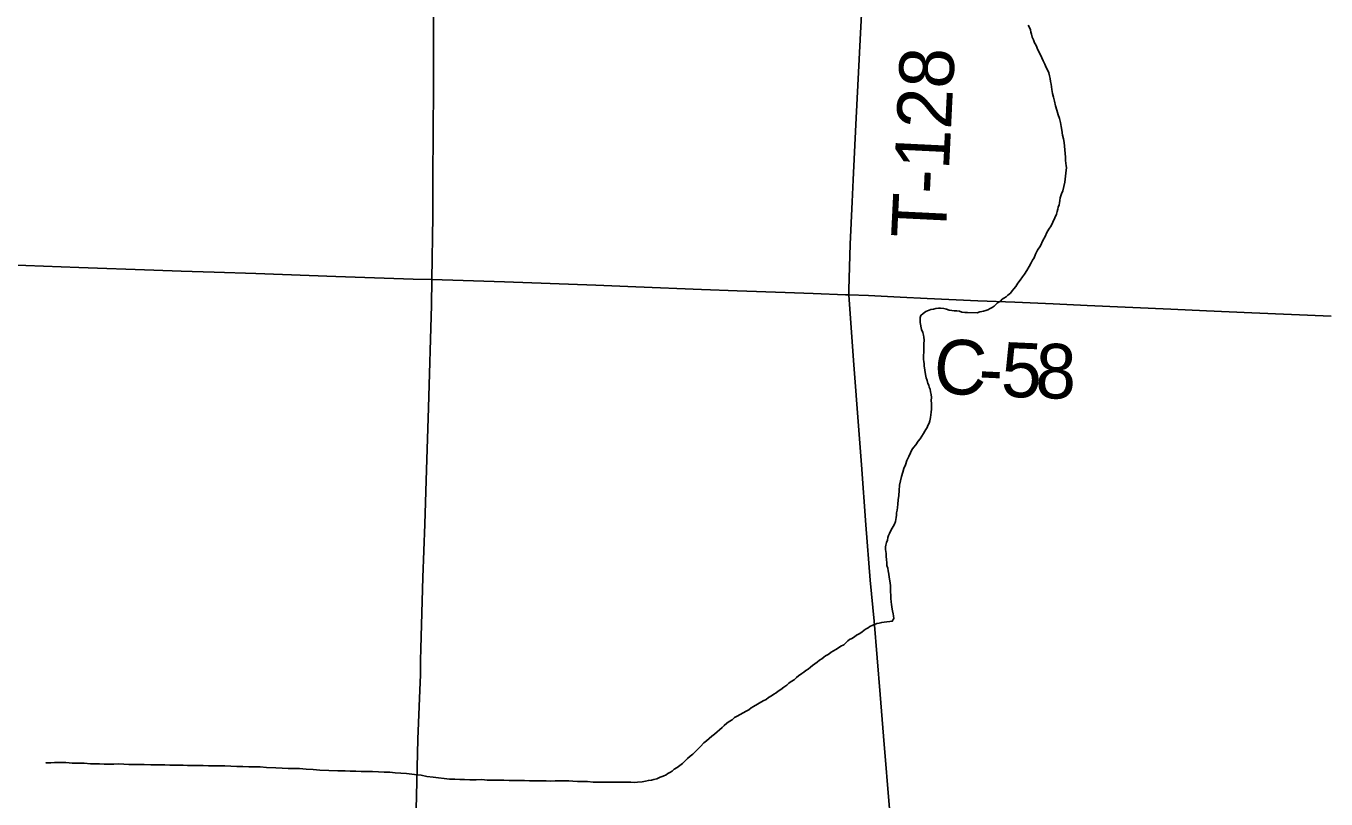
# Model space of a CAD drawing. Extents: x 2.1 to 73.9, y 4 to 26.
# Drawn here: x 43.974 to 44.65, y 24.1 to 24.503 of the extents above; entities that cross this region are included whole.
import ezdxf

# ---------------------------------------------------------------- set-up
doc = ezdxf.new("R2010")
doc.units = 0
for name, color, linetype in [('GM_X_County_Road', 7, 'Continuous'), ('GM_X_County_Road_Text', 7, 'Continuous'), ('GM_X_Minor_River', 7, 'Continuous'), ('GM_X_Township_Road', 7, 'Continuous'), ('GM_X_Township_Road_Text', 7, 'Continuous'), ('GM_X_US_Route', 7, 'Continuous')]:
    doc.layers.add(name, color=color, linetype=linetype)

msp = doc.modelspace()

# ---------------------------------------------------------------- linework, layer by layer
at = {"layer": 'GM_X_County_Road'}
for points in [[(43.67911, 24.38566), (43.68693, 24.38705), (43.69061, 24.38748), (43.69462, 24.38771), (43.69957, 24.38775), (43.70951, 24.38754), (43.73125, 24.38671), (43.74648, 24.3862), (43.78996, 24.38451), (43.8201, 24.38351), (43.84309, 24.38263), (43.86297, 24.38194), (43.88378, 24.38119), (43.90708, 24.38035), (43.93443, 24.37951), (43.96487, 24.37841), (44.00175, 24.37712), (44.04068, 24.37576), (44.05496, 24.37523), (44.07206, 24.37468), (44.0938, 24.3739), (44.13543, 24.37248), (44.17551, 24.37109), (44.18536, 24.37079)], [(44.18536, 24.37079), (44.2016, 24.37028), (44.22304, 24.36954), (44.27057, 24.36784), (44.29139, 24.36705), (44.32555, 24.36564), (44.34419, 24.36496), (44.36904, 24.36408), (44.38364, 24.36357), (44.40041, 24.36294), (44.40217, 24.3629)], [(44.40217, 24.3629), (44.41252, 24.36245), (44.42897, 24.36156), (44.44295, 24.36099), (44.46935, 24.35979), (44.48861, 24.35897), (44.50848, 24.35817), (44.52618, 24.35737), (44.56966, 24.35545), (44.58829, 24.35453), (44.61189, 24.35347), (44.65309, 24.35168)]]:
    msp.add_lwpolyline(points, dxfattribs=at)
at = {"layer": 'GM_X_Minor_River'}
for points in [[(44.49559, 24.50322), (44.49595, 24.50226), (44.49669, 24.50073), (44.49686, 24.49959), (44.49722, 24.49844), (44.49758, 24.49692), (44.49832, 24.49557), (44.49887, 24.49405), (44.49942, 24.4929), (44.49997, 24.49175), (44.50034, 24.49079), (44.50089, 24.48983), (44.50255, 24.4862), (44.50328, 24.48467), (44.50421, 24.48294), (44.50494, 24.48122), (44.50567, 24.47969), (44.50622, 24.47835), (44.50658, 24.47682), (44.50694, 24.47549), (44.50711, 24.47397), (44.50746, 24.47244), (44.5078, 24.46978), (44.50815, 24.46768), (44.50869, 24.46577), (44.50923, 24.46368), (44.50976, 24.4612), (44.51048, 24.45891), (44.5112, 24.45661), (44.51174, 24.45471), (44.51228, 24.45261), (44.51263, 24.45051), (44.51298, 24.44861), (44.51332, 24.44594), (44.51386, 24.44403), (44.51421, 24.44213), (44.51437, 24.44023), (44.51453, 24.43832), (44.51469, 24.43642), (44.51485, 24.43452), (44.51501, 24.433), (44.51518, 24.43128), (44.51535, 24.43014), (44.51552, 24.429), (44.51531, 24.42767), (44.51464, 24.42141), (44.51362, 24.41706), (44.51283, 24.41536), (44.51223, 24.41328), (44.51202, 24.41196), (44.51181, 24.41082), (44.5116, 24.40969), (44.5112, 24.40855), (44.51099, 24.40742), (44.5106, 24.40628), (44.51019, 24.40477), (44.5094, 24.40288), (44.50841, 24.40062), (44.50743, 24.39873), (44.50626, 24.39704), (44.50529, 24.39535), (44.5043, 24.39327), (44.50313, 24.3912), (44.50194, 24.38837)], [(44.50194, 24.38837), (44.50039, 24.38612), (44.4994, 24.38405), (44.49861, 24.38216), (44.49783, 24.38084), (44.49705, 24.37952), (44.49607, 24.37764), (44.49489, 24.37557), (44.49353, 24.37369), (44.49256, 24.37219), (44.49139, 24.3705), (44.49022, 24.369), (44.48905, 24.36711), (44.48808, 24.36599), (44.48711, 24.36487), (44.48634, 24.36374), (44.48499, 24.36262), (44.48402, 24.36188), (44.48287, 24.36114), (44.48191, 24.36058), (44.48114, 24.35964), (44.4796, 24.35872), (44.47786, 24.35704), (44.47671, 24.35629), (44.47575, 24.35574), (44.47459, 24.355), (44.47345, 24.35464), (44.4723, 24.35428), (44.47135, 24.3541), (44.47039, 24.35393), (44.46906, 24.35357), (44.46392, 24.35365), (44.46259, 24.35367), (44.46107, 24.35389), (44.45975, 24.35429), (44.45842, 24.3545), (44.45709, 24.35452), (44.45576, 24.35473), (44.45443, 24.35494), (44.45311, 24.35534), (44.45159, 24.35575), (44.44988, 24.35597), (44.44893, 24.35598), (44.44741, 24.35582), (44.44626, 24.35545), (44.44493, 24.35528), (44.44397, 24.35492), (44.44225, 24.35419), (44.4409, 24.35307), (44.43974, 24.35214), (44.43934, 24.35101), (44.43933, 24.34987), (44.43931, 24.34854), (44.43948, 24.34758), (44.43983, 24.34568), (44.44001, 24.34473), (44.44074, 24.34319), (44.4411, 24.34186), (44.44128, 24.34091), (44.44144, 24.33919), (44.44122, 24.3373), (44.44119, 24.33559), (44.44115, 24.33312), (44.44112, 24.33103), (44.44109, 24.32932), (44.44126, 24.32799), (44.44144, 24.32704), (44.44142, 24.3259), (44.44211, 24.32133), (44.44246, 24.31961), (44.44301, 24.31827), (44.44336, 24.31675), (44.44392, 24.31579), (44.44409, 24.31484), (44.44446, 24.31369), (44.44463, 24.31236), (44.44498, 24.31102), (44.44515, 24.3095), (44.44512, 24.30779), (44.44529, 24.30627), (44.44527, 24.30494), (44.44524, 24.30342), (44.44503, 24.30172), (44.44479, 24.29906), (44.44439, 24.29736), (44.44399, 24.29603), (44.4434, 24.2949), (44.443, 24.29377), (44.44222, 24.29283), (44.44183, 24.29189), (44.44105, 24.29076), (44.44026, 24.28925), (44.43929, 24.28794), (44.43832, 24.28663), (44.43715, 24.28475), (44.4358, 24.28344), (44.43501, 24.28212), (44.43423, 24.28061), (44.43344, 24.27873), (44.43246, 24.27665), (44.43166, 24.27439)], [(44.43166, 24.27439), (44.43087, 24.2725), (44.43027, 24.27061), (44.42966, 24.26834), (44.42905, 24.26607), (44.42864, 24.2638), (44.4284, 24.26095), (44.42817, 24.25849), (44.42794, 24.25621), (44.42772, 24.25393), (44.4275, 24.25223), (44.42729, 24.25071), (44.42707, 24.24939), (44.42706, 24.24825), (44.42685, 24.24692), (44.42664, 24.24597), (44.42643, 24.24484), (44.42603, 24.24351), (44.42407, 24.24013), (44.42329, 24.23862), (44.42289, 24.23768), (44.4225, 24.23654), (44.42228, 24.23522), (44.42188, 24.23389), (44.42148, 24.23257), (44.42128, 24.23162), (44.42126, 24.2303), (44.42143, 24.22934), (44.4216, 24.2282), (44.42158, 24.22668), (44.42174, 24.22516), (44.42191, 24.22345), (44.42207, 24.22192), (44.42243, 24.22059), (44.4226, 24.21926), (44.42295, 24.21754), (44.42312, 24.21583), (44.42347, 24.21392), (44.42364, 24.21278), (44.42381, 24.21164), (44.42398, 24.2105), (44.42396, 24.20936), (44.42394, 24.20803), (44.42411, 24.2067), (44.42408, 24.2048), (44.42424, 24.20309), (44.42441, 24.20175), (44.42458, 24.20042), (44.42475, 24.19928), (44.42493, 24.19833), (44.42529, 24.1968), (44.42546, 24.19585), (44.42563, 24.19432), (44.42484, 24.19301), (44.42351, 24.19284), (44.42199, 24.19267), (44.42065, 24.19251), (44.41932, 24.19234), (44.41798, 24.19198), (44.41684, 24.19181), (44.41473, 24.19089), (44.4132, 24.19016), (44.41224, 24.1896), (44.41128, 24.18905), (44.41012, 24.18831), (44.40897, 24.18737), (44.40762, 24.18645), (44.40628, 24.18571), (44.40512, 24.18478), (44.40378, 24.18404), (44.40263, 24.18349), (44.40167, 24.18274), (44.4007, 24.18181), (44.39954, 24.18069), (44.39801, 24.17995), (44.39686, 24.17921), (44.39551, 24.17828), (44.39417, 24.17755), (44.39301, 24.1768), (44.39205, 24.17606), (44.39109, 24.1755), (44.39013, 24.17495), (44.38917, 24.17421), (44.38821, 24.17346), (44.38705, 24.17272), (44.3857, 24.1716), (44.38455, 24.17086), (44.38339, 24.16993), (44.38224, 24.169), (44.38108, 24.16807), (44.37993, 24.16733), (44.37877, 24.16639), (44.37781, 24.16584), (44.37608, 24.16454), (44.37492, 24.16361), (44.37376, 24.16249), (44.37223, 24.16156), (44.37108, 24.16082), (44.36992, 24.1597), (44.36838, 24.15858), (44.36684, 24.15747)], [(44.36684, 24.15747), (44.36549, 24.15654), (44.36434, 24.1558), (44.36319, 24.15506), (44.36203, 24.15413), (44.36049, 24.1532), (44.35915, 24.15227), (44.35761, 24.15154), (44.35262, 24.14858), (44.35147, 24.14784), (44.35012, 24.14691), (44.34878, 24.14617), (44.34724, 24.14525), (44.34571, 24.14451), (44.34417, 24.14359), (44.34283, 24.14285), (44.34148, 24.14173), (44.33994, 24.1408), (44.33879, 24.13987), (44.33744, 24.13876), (44.33628, 24.13764), (44.33493, 24.13652), (44.33377, 24.1354), (44.33242, 24.13428), (44.33088, 24.13316), (44.32953, 24.13186), (44.32818, 24.13074), (44.32683, 24.12962), (44.32509, 24.12775), (44.32374, 24.12644), (44.32239, 24.12513), (44.32103, 24.12382), (44.31969, 24.12271), (44.31834, 24.12159), (44.31717, 24.12028), (44.31563, 24.11897), (44.31428, 24.11786), (44.31294, 24.11693), (44.3114, 24.116), (44.31024, 24.11488), (44.30909, 24.11433), (44.30813, 24.11377), (44.30717, 24.11303), (44.30564, 24.11229), (44.3041, 24.11175), (44.30238, 24.11102), (44.30085, 24.11066), (44.29952, 24.1103), (44.29799, 24.11014), (44.29647, 24.10978), (44.29475, 24.10943), (44.29227, 24.10928), (44.29056, 24.10912), (44.28885, 24.10914), (44.28676, 24.10918), (44.28467, 24.10921), (44.28257, 24.10925), (44.2801, 24.10928), (44.27363, 24.1092), (44.27135, 24.10924), (44.26926, 24.10927), (44.26622, 24.10951), (44.26375, 24.10955), (44.26109, 24.10959), (44.25862, 24.10982), (44.25653, 24.10985), (44.25406, 24.10989), (44.25196, 24.10993), (44.24949, 24.10997), (44.24721, 24.10981), (44.24474, 24.10985), (44.24226, 24.10989), (44.23884, 24.10995), (44.23618, 24.10999), (44.23352, 24.11003), (44.23085, 24.11008), (44.22819, 24.11012), (44.22553, 24.11016), (44.22268, 24.11021), (44.21983, 24.11025), (44.21698, 24.1103), (44.21412, 24.11034), (44.21127, 24.11058), (44.20842, 24.11043), (44.205, 24.11049), (44.20233, 24.11053), (44.19986, 24.11057), (44.1972, 24.1108), (44.19454, 24.11085), (44.19169, 24.11108), (44.18885, 24.11151), (44.186, 24.11174), (44.18277, 24.11218), (44.17974, 24.11279), (44.17632, 24.11323), (44.17214, 24.11368), (44.1691, 24.11391), (44.16625, 24.11415), (44.16341, 24.11439), (44.16055, 24.11443), (44.15751, 24.11467)], [(44.15751, 24.11467), (44.15447, 24.11472), (44.15162, 24.11477), (44.14858, 24.11481), (44.14573, 24.11486), (44.14287, 24.11491), (44.14021, 24.11514), (44.13641, 24.1152), (44.1271, 24.11554), (44.12349, 24.11579), (44.11988, 24.11603), (44.11646, 24.11628), (44.11342, 24.11633), (44.11057, 24.11637), (44.10752, 24.11642), (44.1041, 24.11667), (44.09935, 24.11693), (44.09593, 24.11718), (44.09289, 24.11723), (44.09004, 24.11727), (44.087, 24.11732), (44.08395, 24.11737), (44.08072, 24.11761), (44.07768, 24.11766), (44.07483, 24.11771), (44.07198, 24.11775), (44.06913, 24.1178), (44.06627, 24.11784), (44.06304, 24.1179), (44.06057, 24.11794), (44.05829, 24.11797), (44.05601, 24.11801), (44.05373, 24.11805), (44.05144, 24.11808), (44.04897, 24.11812), (44.0465, 24.11816), (44.04403, 24.1182), (44.04156, 24.11824), (44.03908, 24.11828), (44.03566, 24.11834), (44.03319, 24.11837), (44.03053, 24.11842), (44.02768, 24.11846), (44.02501, 24.11851), (44.02235, 24.11874), (44.01988, 24.11859), (44.01741, 24.11863), (44.01494, 24.11867), (44.01246, 24.11871), (44.00999, 24.11875), (44.00771, 24.11878), (44.00448, 24.11903), (44.0022, 24.11906), (44.00011, 24.1191), (43.99821, 24.11913), (43.99669, 24.11934), (43.99498, 24.11937), (43.99346, 24.11939), (43.98908, 24.11946), (43.98718, 24.1193), (43.98566, 24.11933), (43.98452, 24.11935), (43.98452, 24.11935)]]:
    msp.add_lwpolyline(points, dxfattribs=at)
at = {"layer": 'GM_X_Township_Road'}
for points in [[(44.40217, 24.3629), (44.40216, 24.36554), (44.40296, 24.38915), (44.404, 24.4112), (44.40452, 24.42269), (44.40595, 24.45156), (44.4083, 24.49906), (44.40961, 24.52545), (44.41025, 24.53974), (44.41144, 24.56302), (44.41224, 24.57948), (44.41293, 24.59252), (44.41375, 24.61115), (44.41384, 24.6133)], [(44.44166, 23.85882), (44.4416, 23.86177), (44.44144, 23.86556), (44.44121, 23.86944), (44.43903, 23.8968), (44.43635, 23.93306), (44.43345, 23.96962), (44.43179, 23.98976), (44.42927, 24.02136), (44.42694, 24.05111), (44.42525, 24.07218), (44.42352, 24.09324), (44.4202, 24.1332), (44.41846, 24.15488), (44.41534, 24.19298), (44.41336, 24.21434), (44.41115, 24.24316), (44.40875, 24.27446), (44.40747, 24.29244), (44.40463, 24.3287), (44.40217, 24.3629)]]:
    msp.add_lwpolyline(points, dxfattribs=at)
at = {"layer": 'GM_X_US_Route'}
msp.add_lwpolyline([(44.17596, 24.04831), (44.17725, 24.10207), (44.17809, 24.13159), (44.17902, 24.15706), (44.17934, 24.16514), (44.17942, 24.17261), (44.1795, 24.17882), (44.18063, 24.21579), (44.18171, 24.24344), (44.18249, 24.27171), (44.18362, 24.30402), (44.18516, 24.35748), (44.18536, 24.37079), (44.18585, 24.4038), (44.18584, 24.4237), (44.18592, 24.44732), (44.18622, 24.47094), (44.18616, 24.49426), (44.18624, 24.51477)], dxfattribs=at)

# ---------------------------------------------------------------- texts
at = {"layer": 'GM_X_County_Road_Text'}
for s, rotation, p in [('C', 357.22004, (44.4459, 24.3117)), ('5', 357.4542, (44.48098, 24.31001)), ('8', 358.41938, (44.49899, 24.30921)), ('-', 357.26429, (44.46923, 24.31057))]:
    msp.add_text(s, height=0.02841, rotation=rotation, dxfattribs=at).set_placement(p)
at = {"layer": 'GM_X_Township_Road_Text'}
msp.add_text('T-128', height=0.028409, rotation=87.19323, dxfattribs=at).set_placement((44.45255, 24.39174))

doc.saveas('drawing.dxf')
